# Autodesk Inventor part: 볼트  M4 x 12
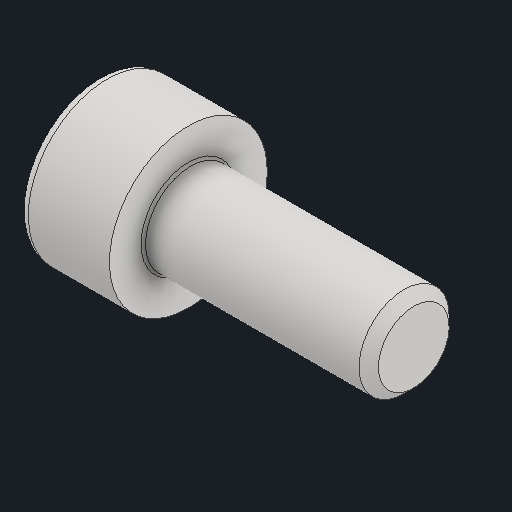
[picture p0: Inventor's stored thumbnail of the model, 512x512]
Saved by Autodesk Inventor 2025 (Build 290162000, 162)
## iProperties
Created: 2025-08
Part Number: 볼트  M4 x 12
Material: 스테인리스강
Description: 6각머리 태핑 나사
Document SubType Name: Modeling
Designer: infra08
Density: 8.08 g/cm^3
Appearance: 기본값
Author: jhkim
Sending System: Autodesk Inventor 2026
Preprocessor: ST-DEVELOPER v20.1
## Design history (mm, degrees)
feature "Solid1"
node "솔리드1"
